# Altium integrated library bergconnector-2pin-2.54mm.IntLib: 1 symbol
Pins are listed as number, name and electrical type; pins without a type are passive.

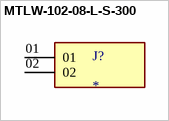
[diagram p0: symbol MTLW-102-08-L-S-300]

## MTLW-102-08-L-S-300
designator J?
MP: MTLW-102-08-L-S-300
footprint SAMTEC_MTLW-102-08-L-S-300
pins: 01, 02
